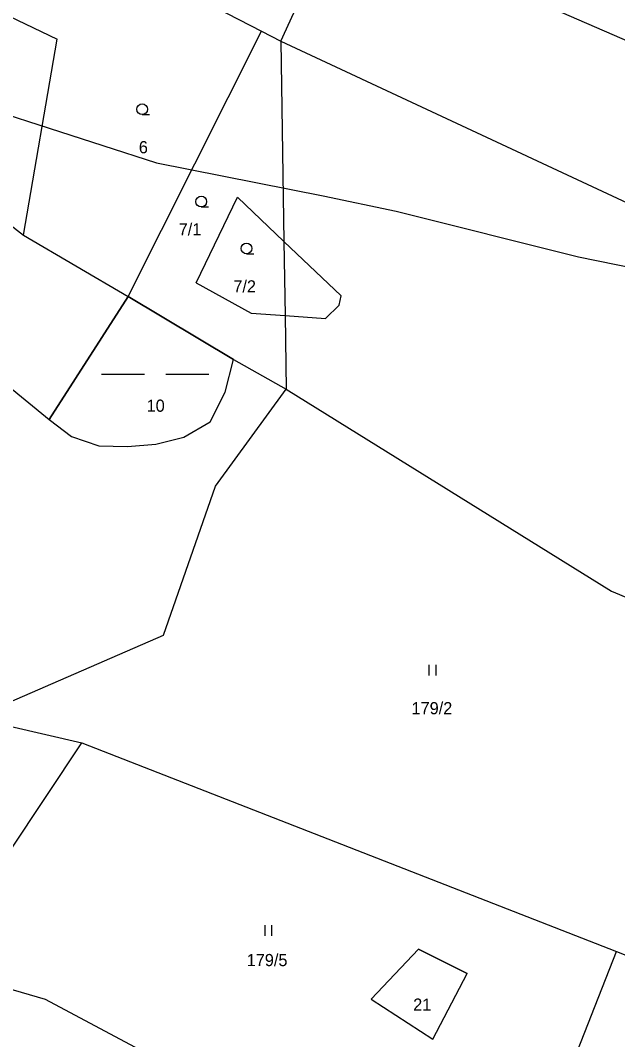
# Model space of a CAD drawing. Extents: x -743888 to -742027, y -1128394 to -1126768.
# Drawn here: x -742827 to -742743.6, y -1127574.7 to -1127432.2 of the extents above; entities that cross this region are included whole.
import ezdxf

# ---------------------------------------------------------------- set-up
doc = ezdxf.new("R2010")
doc.units = 0
for name, color, linetype in [('Vrstva 1', 7, 'Continuous'), ('Vrstva 18', 7, 'Continuous'), ('Vrstva 25', 7, 'Continuous'), ('Vrstva 4', 7, 'Continuous'), ('Vrstva 52', 7, 'Continuous'), ('Vrstva 6', 7, 'Continuous')]:
    doc.layers.add(name, color=color, linetype=linetype)

msp = doc.modelspace()

# ---------------------------------------------------------------- linework, layer by layer
at = {"layer": 'Vrstva 1'}
for points in [[(-742822, -1127418.91), (-742793.34, -1127433.72)], [(-742839.78, -1127426.23), (-742821.85, -1127434.87)], [(-742826.58, -1127462.26), (-742821.85, -1127434.87)], [(-742811.96, -1127470.81), (-742793.34, -1127433.72)], [(-742837, -1127454.13), (-742826.58, -1127462.26)], [(-742802.46, -1127468.89), (-742796.68, -1127456.92)], [(-742796.68, -1127456.92), (-742790.19, -1127463.11)], [(-742826.58, -1127462.26), (-742811.96, -1127470.81)], [(-742802.46, -1127468.89), (-742794.75, -1127473.16)], [(-742822.98, -1127487.99), (-742811.96, -1127470.81)], [(-742811.96, -1127470.81), (-742797.22, -1127479.6)], [(-742794.75, -1127473.16), (-742790.03, -1127473.49)], [(-742798.37, -1127484.18), (-742797.22, -1127479.6)], [(-742829.18, -1127482.91), (-742822.98, -1127487.99)], [(-742800.5, -1127488.35), (-742798.37, -1127484.18)], [(-742822.98, -1127487.99), (-742819.83, -1127490.36)], [(-742804.15, -1127490.46), (-742800.5, -1127488.35)], [(-742819.83, -1127490.36), (-742816.03, -1127491.67)], [(-742816.03, -1127491.67), (-742812.05, -1127491.77)], [(-742812.05, -1127491.77), (-742808.08, -1127491.47)], [(-742808.08, -1127491.47), (-742804.15, -1127490.46)], [(-742833.52, -1127529.71), (-742818.41, -1127533.18)], [(-742838.56, -1127563.45), (-742818.41, -1127533.18)], [(-742818.41, -1127533.18), (-742743.76, -1127562.35)], [(-742778, -1127569), (-742771.4, -1127562)], [(-742771.4, -1127562), (-742764.6, -1127565.4)], [(-742743.76, -1127562.35), (-742730.61, -1127567.49)], [(-742769.4, -1127574.6), (-742764.6, -1127565.4)], [(-742778, -1127569), (-742769.4, -1127574.6)]]:
    msp.add_lwpolyline(points, dxfattribs=at)
at = {"layer": 'Vrstva 25'}
for p, q in [((-742809.98, -1127445.4), (-742808.98, -1127445.4)), ((-742801.73, -1127458.3), (-742800.73, -1127458.3)), ((-742795.41, -1127464.85), (-742794.41, -1127464.85)), ((-742815.66, -1127481.67), (-742809.66, -1127481.67)), ((-742806.66, -1127481.67), (-742800.66, -1127481.67)), ((-742769.94, -1127522.29), (-742769.94, -1127523.79)), ((-742768.94, -1127523.79), (-742768.94, -1127522.29)), ((-742792.86, -1127558.64), (-742792.86, -1127560.14)), ((-742791.86, -1127560.14), (-742791.86, -1127558.64))]:
    msp.add_line(p, q, dxfattribs=at)
for centre in [(-742809.98, -1127444.65), (-742801.73, -1127457.55), (-742795.41, -1127464.1)]:
    msp.add_circle(centre, 0.75, dxfattribs=at)
at = {"layer": 'Vrstva 4'}
for points in [[(-742790.19, -1127463.11), (-742782.21, -1127470.73)], [(-742782.45, -1127472.04), (-742782.21, -1127470.73)], [(-742784.4, -1127473.88), (-742782.45, -1127472.04)], [(-742790.03, -1127473.49), (-742784.4, -1127473.88)]]:
    msp.add_lwpolyline(points, dxfattribs=at)
at = {"layer": 'Vrstva 52'}
for points in [[(-742883.68, -1127406.25), (-742877.77, -1127411.74), (-742873.23, -1127415.96), (-742864.44, -1127424.13), (-742863.69, -1127424.62), (-742845.38, -1127436.88), (-742839.38, -1127440.25), (-742840.69, -1127443.25), (-742830.5, -1127444.88), (-742808, -1127452.13), (-742784.69, -1127456.75), (-742774.5, -1127458.88), (-742749.06, -1127465.25), (-742728.25, -1127469.5)], [(-742798.37, -1127484.18), (-742797.22, -1127479.6), (-742811.96, -1127470.81), (-742822.98, -1127487.99), (-742819.83, -1127490.36), (-742816.03, -1127491.67), (-742812.05, -1127491.77), (-742808.08, -1127491.47), (-742804.15, -1127490.46), (-742800.5, -1127488.35), (-742798.37, -1127484.18)], [(-742769.4, -1127574.6), (-742764.6, -1127565.4), (-742771.4, -1127562), (-742778, -1127569), (-742769.4, -1127574.6)]]:
    msp.add_lwpolyline(points, dxfattribs=at)
at = {"layer": 'Vrstva 6'}
for points in [[(-742790.61, -1127435.15), (-742782.56, -1127417.54)], [(-742782.56, -1127417.54), (-742741.92, -1127435.21)], [(-742793.34, -1127433.72), (-742790.61, -1127435.15)], [(-742790.61, -1127435.15), (-742790.19, -1127463.11)], [(-742790.61, -1127435.15), (-742721.92, -1127467.25)], [(-742790.19, -1127463.11), (-742790.03, -1127473.49)], [(-742790.03, -1127473.49), (-742789.88, -1127483.77)], [(-742797.22, -1127479.6), (-742789.88, -1127483.77)], [(-742799.72, -1127497.31), (-742789.88, -1127483.77)], [(-742789.88, -1127483.77), (-742744.44, -1127512)], [(-742807.02, -1127518.12), (-742799.72, -1127497.31)], [(-742744.44, -1127512), (-742714.26, -1127524.61)], [(-742831.78, -1127528.92), (-742807.02, -1127518.12)], [(-742758.22, -1127599.23), (-742743.76, -1127562.35)], [(-742829.14, -1127567.37), (-742823.54, -1127569.02)], [(-742823.54, -1127569.02), (-742788.73, -1127587.57)]]:
    msp.add_lwpolyline(points, dxfattribs=at)

# ---------------------------------------------------------------- texts
at = {"layer": 'Vrstva 18'}
for s, p in [('6', (-742810.45, -1127450.8)), ('7/1', (-742804.88, -1127462.27)), ('7/2', (-742797.25, -1127470.25)), ('10', (-742809.36, -1127486.92)), ('179/2', (-742772.36, -1127529.19)), ('179/5', (-742795.38, -1127564.39)), ('21', (-742772.13, -1127570.61))]:
    msp.add_text(s, height=1.7, dxfattribs=at).set_placement(p)

doc.saveas('drawing.dxf')
